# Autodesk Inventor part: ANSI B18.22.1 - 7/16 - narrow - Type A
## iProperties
Comments: To add or edit properties for Autodesk Inventor files, use iProperties.
Created: 2005-06
Part Number: ANSI B18.22.1 - 7/16 - narrow - Type A
Vendor: Autodesk Inc.
Document SubType Name: Modeling
Designer: John Blackburn
Material: Default
Description: Washer A
Standard: ANSI B18.22.1
Alert: To add or edit properties for Autodesk Inventor files, use iProperties.
Control State: 0
Master: False
Checked Out: False
Shininess: 64.0
Length Units: 11272
Angle Units: 11279
Time Units: 11290
Mass Units: 11286
Length Display Precision: 3
Angle Display Precision: 2
Compacted: True
Classification: un/spsc 31161807
Density: 0.0
Volumn: 0.0
Area: 0.0
PropertySet Name: Model Information
Author: John Blackburn
Revision Number: 8
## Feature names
1. Body [Extrusion]
